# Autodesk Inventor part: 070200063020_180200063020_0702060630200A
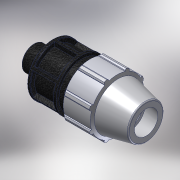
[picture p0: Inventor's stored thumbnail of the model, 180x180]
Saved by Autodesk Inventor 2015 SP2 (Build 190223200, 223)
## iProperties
Created: 2017-02
Part Number: 070200063020_180200063020_0702060630200A
Material: PVC-Piping
Description: PLASSON MALE ADAPTOR 63-2"
Document SubType Name: Modeling
Designer: KIM
Mass: 92.6774 g
Surface Area: 199.44 cm^2
Volume: 66.1981 cm^3
Density: 1.4 g/cm^3
Appearance: PTFE
Author: KIM
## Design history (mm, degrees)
derived "07020.ipt"
feature "Solid1::07020.ipt"
tag "TaggingFeature1"
body "Solid1"
other parameters: "d2" = 63, "d4" = 23.85714, "d5" = 41.75, "d7" = 113, "d8" = 84.75, "d9" = 23.85714, "d11" = 4.77143, "d12" = 90.4, "d13" = 120 deg, "d14" = 88.2, "d15" = 6 deg, "d16" = 101.7, "d18" = 3.15, "d19" = 35 deg, "d20" = 17.5 deg, "d21" = 105.09, "d23" = 0, "d25" = 360 deg, "d27" = 2.26, "d34" = 5.65, "d36" = 0, "d42" = 41.75, "d43" = 3.39, "d46" = 1.89, "d49" = 123, "d51" = 167, "d52" = 26, "d53" = 1.26, "d55" = 360 deg, "d57" = 59.614, "d58" = 41.7298, "d59" = 33.4, "d_" = 63, "E_" = 113, "H_" = 167, "l_" = 123, "l_2" = 26, "R_" = 59.614
